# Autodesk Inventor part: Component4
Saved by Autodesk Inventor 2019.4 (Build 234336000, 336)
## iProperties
Created: 2020-06
Part Number: Component4
Material: Generic
Document SubType Name: Modeling
Designer: Administrator
Density: 1 g/cm^3
Appearance: Default
Title: Component4
Author: Administrator
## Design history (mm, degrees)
